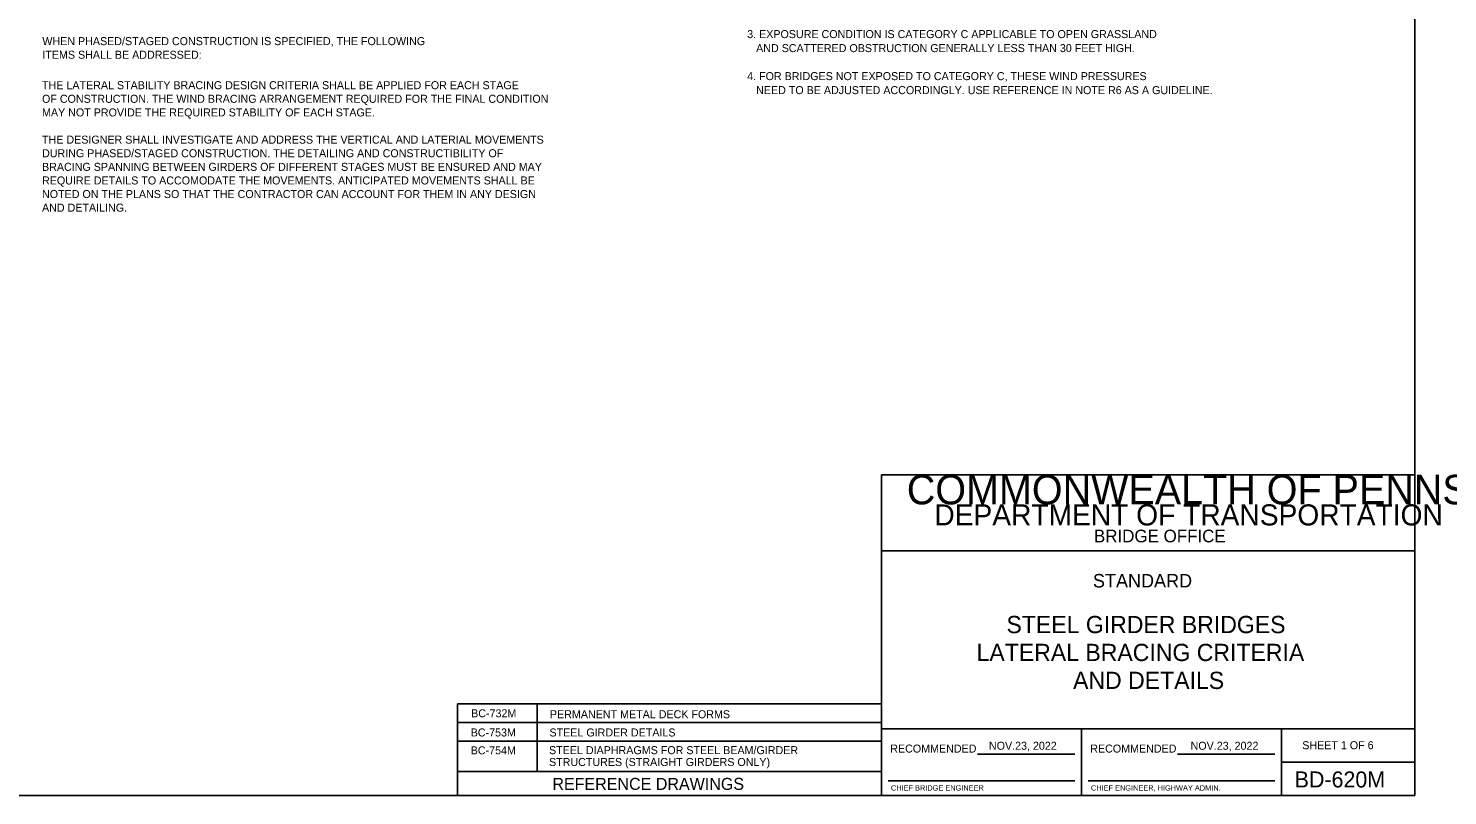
# Model space of a CAD drawing. Extents: x 30 to 2621, y -33 to 1155.
# Drawn here: x 337 to 869, y 576 to 864 of the extents above; entities that cross this region are included whole.
import ezdxf

# ---------------------------------------------------------------- set-up
doc = ezdxf.new("R2010")
doc.units = 0
for name, color, linetype in [('1', 7, 'Continuous'), ('2', 7, 'Continuous'), ('SIGNATORY TITLES', 7, 'Continuous')]:
    doc.layers.add(name, color=color, linetype=linetype)

msp = doc.modelspace()

# ---------------------------------------------------------------- linework, layer by layer
at = {"layer": '1'}
for p, q in [((856.5, 576), (856.5, 1140)), ((656.5, 696.23), (856.5, 696.23)), ((656.5, 696.23), (656.5, 576)), ((656.5, 667.75), (856.5, 667.75)), ((856.5, 601), (656.5, 601)), ((731.5, 576), (731.5, 601)), ((806.5, 601), (806.5, 576)), ((692.59, 591.5), (729, 591.5)), ((767.59, 591.5), (804, 591.5)), ((806.5, 588.5), (856.5, 588.5)), ((659, 581.5), (729, 581.5)), ((734, 581.5), (804, 581.5)), ((70.5, 576), (856.5, 576))]:
    msp.add_line(p, q, dxfattribs=at)
at = {"layer": '2'}
for p, q in [((497.61, 610.43), (497.61, 576)), ((497.61, 610.43), (656.5, 610.43)), ((527.48, 585), (527.48, 610.43)), ((497.61, 603.43), (656.5, 603.43)), ((497.61, 596.43), (656.5, 596.43)), ((856.5, 601), (656.5, 601)), ((497.61, 585), (656.5, 585))]:
    msp.add_line(p, q, dxfattribs=at)

# ---------------------------------------------------------------- texts
at = {"layer": '1'}
for s, height, p in [('  3. EXPOSURE CONDITION IS CATEGORY C APPLICABLE TO OPEN GRASSLAND', 3, (603.96, 859.9)), ('WHEN PHASED/STAGED CONSTRUCTION IS SPECIFIED, THE FOLLOWING', 3, (341.88, 857.26)), ('     AND SCATTERED OBSTRUCTION GENERALLY LESS THAN 30 FEET HIGH.', 3, (603.96, 854.65)), ('ITEMS SHALL BE ADDRESSED:', 3, (341.88, 852.16)), ('  4. FOR BRIDGES NOT EXPOSED TO CATEGORY C, THESE WIND PRESSURES', 3, (603.96, 844.15)), ('THE LATERAL STABILITY BRACING DESIGN CRITERIA SHALL BE APPLIED FOR EACH STAGE', 3, (341.76, 840.75)), ('     NEED TO BE ADJUSTED ACCORDINGLY. USE REFERENCE IN NOTE R6 AS A GUIDELINE.', 3, (603.96, 838.9)), ('OF CONSTRUCTION. THE WIND BRACING ARRANGEMENT REQUIRED FOR THE FINAL CONDITION', 3, (341.76, 835.65)), ('MAY NOT PROVIDE THE REQUIRED STABILITY OF EACH STAGE.', 3, (341.76, 830.55)), ('THE DESIGNER SHALL INVESTIGATE AND ADDRESS THE VERTICAL AND LATERIAL MOVEMENTS', 3, (341.76, 820.35)), ('DURING PHASED/STAGED CONSTRUCTION. THE DETAILING AND CONSTRUCTIBILITY OF', 3, (341.76, 815.25)), ('BRACING SPANNING BETWEEN GIRDERS OF DIFFERENT STAGES MUST BE ENSURED AND MAY', 3, (341.76, 810.15)), ('REQUIRE DETAILS TO ACCOMODATE THE MOVEMENTS. ANTICIPATED MOVEMENTS SHALL BE', 3, (341.76, 805.05)), ('NOTED ON THE PLANS SO THAT THE CONTRACTOR CAN ACCOUNT FOR THEM IN ANY DESIGN', 3, (341.76, 799.95)), ('AND DETAILING.', 3, (341.76, 794.85)), ('COMMONWEALTH OF PENNSYLVANIA', 11.0789, (666.03, 685.15)), ('COMMONWEALTH OF PENNSYLVANIA', 11.0789, (666.03, 685.15)), ('DEPARTMENT OF TRANSPORTATION', 7.8962, (676.38, 677.25)), ('DEPARTMENT OF TRANSPORTATION', 7.8962, (676.38, 677.25)), ('BRIDGE OFFICE', 4.7495, (736.22, 670.92)), ('STANDARD', 5.055, (735.84, 654)), ('STEEL GIRDER BRIDGES', 6.4601, (703.41, 636.88)), ('LATERAL BRACING CRITERIA', 6.4601, (692.2, 626.42)), ('AND DETAILS', 6.4601, (728.39, 615.96)), ('SHEET 1 OF 6', 3, (814.33, 593.38)), ('RECOMMENDED', 3, (659.83, 592.12)), ('RECOMMENDED', 3, (734.83, 592.12)), ('BD-620M', 6, (811.5, 579.06))]:
    msp.add_text(s, height=height, dxfattribs=at).set_placement(p)
at = {"layer": '2'}
for s, height, p in [('BC-732M', 3, (502.67, 605.34)), ('PERMANENT METAL DECK FORMS', 3, (532.22, 604.99)), ('BC-753M', 3, (502.51, 598.16)), ('STEEL GIRDER DETAILS', 3, (532.04, 598.16)), ('BC-754M', 3, (502.51, 591.46)), ('STEEL DIAPHRAGMS FOR STEEL BEAM/GIRDER', 3, (531.87, 591.53)), ('STRUCTURES (STRAIGHT GIRDERS ONLY)', 3, (531.87, 587.09)), ('REFERENCE DRAWINGS', 4.5, (533.13, 578.14))]:
    msp.add_text(s, height=height, dxfattribs=at).set_placement(p)
at = {"layer": 'SIGNATORY TITLES'}
for s, height, p in [('NOV.23, 2022', 3, (696.84, 593.18)), ('NOV.23, 2022', 3, (772.46, 593.18)), ('CHIEF BRIDGE ENGINEER', 2, (660.09, 577.88)), ('CHIEF ENGINEER, HIGHWAY ADMIN.', 2, (735.09, 577.88))]:
    msp.add_text(s, height=height, dxfattribs=at).set_placement(p)

doc.saveas('drawing.dxf')
